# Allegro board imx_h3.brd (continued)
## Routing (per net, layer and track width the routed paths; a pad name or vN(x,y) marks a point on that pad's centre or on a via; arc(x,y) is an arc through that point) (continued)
DDR2_D14: length 15.4
  INT1 w0.12: v1(68.69,44.35) 68.72,44.37 68.72,44.38 68.56,44.22 66.83,44.22 66.71,44.11 66.6,44.11 66.39,43.9 arc(66.28,43.79) 66.17,43.9 66.17,44 arc(66.06,44.11) 65.95,44 65.95,43.9 arc(65.84,43.79) 65.73,43.9 65.73,44 arc(65.62,44.11) 65.51,44 65.51,43.9 arc(65.4,43.79) 65.29,43.9 65.29,44 arc(65.18,44.11) 65.07,44 65.07,43.9 arc(64.96,43.79) 64.85,43.9 64.85,44 arc(64.74,44.11) 64.63,44 64.63,43.9 arc(64.52,43.79) 64.41,43.9 64.41,44 arc(64.3,44.11) 64.19,44 64.19,43.9 arc(64.08,43.79) 63.97,43.9 63.97,44 arc(63.86,44.11) 63.75,44 63.75,43.9 arc(63.68,43.8) 63.56,43.83 63.37,43.83 63.18,43.65 61.55,43.65 61.48,43.71 61.48,44.36 61.36,44.49 61.25,44.49 61.24,44.49 61.24,44.49 61.23,44.5 60.89,44.5 60.88,44.49 60.35,44.49 arc(60.27,44.52) 60.24,44.6 v1(60.24,44.92)
  BOTTOM w0.12: v1(60.24,44.92) 60.16,44.92 59.84,45.24 ; U2.B1 69.56,45.63 69.37,45.45 68.66,45.45 68.5,45.28 68.5,44.55 v1(68.69,44.35)
DDR2_D15: length 15.3
  BOTTOM w0.12: 63.05,45.24 64.01,45.24 64.92,44.33 66.13,44.33 67.09,43.38 67.55,43.38 arc(67.63,43.34) 67.66,43.26 67.66,43.26 arc(67.77,43.15) 67.88,43.26 67.88,43.26 arc(67.91,43.34) 67.99,43.38 74.31,43.38 75.56,44.62 75.56,45.25 75.96,45.66
DDR2_DQM0: length 16.2
  INT1 w0.12: v1(65.93,49.78) 65.77,49.78 65.47,49.47 65.47,49.24 65.18,48.96 64.31,48.96 63.63,49.63 v1(61.82,49.63)
  BOTTOM w0.12: v1(65.93,49.78) 66.23,49.48 66.23,49.19 67.04,48.37 67.19,48.37 arc(67.27,48.34) 67.3,48.26 67.3,47.62 arc(67.41,47.51) 67.52,47.62 67.52,48.26 arc(67.63,48.37) 67.74,48.26 67.74,47.62 arc(67.85,47.51) 67.96,47.62 67.96,48.26 arc(68.07,48.37) 68.18,48.26 68.18,47.63 arc(68.29,47.52) 68.4,47.63 68.4,48.26 arc(68.44,48.34) 68.51,48.37 69.37,48.37 69.41,48.41 70.5,48.41 70.94,48.85 U2.F3 ; v1(61.82,49.63) 61.82,49.7 61.49,50.03 61.45,50.03
DDR2_DQM1: length 15.3
  INT1 w0.12: v1(61.87,44.78) 62.31,44.33 62.53,44.33 arc(62.59,44.3) 62.62,44.24 arc(62.65,44.18) 62.71,44.15 62.75,44.15 arc(62.81,44.18) 62.84,44.24 arc(62.87,44.3) 62.93,44.33 65.57,44.33 arc(65.62,44.34) 65.65,44.36 65.98,44.69 arc(66.01,44.71) 66.06,44.72 66.23,44.72 arc(66.31,44.69) 66.34,44.61 66.34,44.44 arc(66.45,44.33) 66.56,44.44 66.56,44.61 arc(66.67,44.72) 66.78,44.61 66.78,44.56 arc(66.81,44.48) 66.89,44.44 66.92,44.44 arc(66.98,44.47) 67,44.53 67,44.61 arc(67.11,44.72) 67.22,44.61 67.22,44.53 arc(67.24,44.47) 67.3,44.44 67.33,44.44 arc(67.41,44.48) 67.44,44.56 67.44,44.61 arc(67.47,44.69) 67.55,44.72 67.63,44.72 arc(67.67,44.73) 67.71,44.75 67.79,44.84 arc(67.83,44.86) 67.87,44.87 69.03,44.87 v1(69.01,44.87)
  BOTTOM w0.12: v1(61.87,44.78) 61.81,44.82 61.81,44.87 61.45,45.24 ; U2.B3 71.4,45.66 arc(71.48,45.64) 71.54,45.6 72.32,44.83 arc(72.37,44.69) 72.32,44.56 arc(72.18,44.5) 72.04,44.56 71.44,45.16 arc(71.38,45.2) 71.31,45.22 69.42,45.22 69.07,44.87 69.03,44.87 v1(69.01,44.87)
DDR2_DQS0: length 16.4
  INT1 w0.12: v1(72.81,48.28) 72.59,48.51 71.24,48.51 70.78,48.06 arc(70.71,48.03) 70.63,48.06 70.53,48.16 arc(70.37,48.16) 70.37,48 70.47,47.9 arc(70.47,47.75) 70.32,47.75 70.22,47.85 arc(70.06,47.85) 70.06,47.69 70.16,47.59 arc(70.19,47.52) 70.16,47.44 69.85,47.13 arc(69.82,47.1) 69.77,47.09 69.1,47.09 arc(69.03,47.13) 68.99,47.21 68.99,47.29 arc(68.88,47.4) 68.77,47.29 68.77,47.21 arc(68.66,47.09) 68.55,47.21 68.55,47.29 arc(68.44,47.4) 68.33,47.29 68.33,47.21 arc(68.22,47.09) 68.11,47.21 68.11,47.29 arc(68,47.4) 67.89,47.29 67.89,47.21 arc(67.78,47.09) 67.67,47.21 67.67,47.39 arc(67.56,47.5) 67.45,47.39 67.45,47.21 arc(67.34,47.09) 67.23,47.21 67.23,47.39 arc(67.12,47.5) 67.01,47.39 67.01,47.21 arc(66.98,47.13) 66.9,47.09 66.19,47.09 65.56,47.72 v1(65.38,47.72)
  BOTTOM w0.12: v1(72.81,48.28) 73.12,48.28 73.54,48.71 73.95,48.71 74.09,48.85 U2.F7 ; v1(65.38,47.72) 65.38,47.77 64.91,48.24 64.59,48.24 arc(64.48,48.31) 64.35,48.34 63.14,48.34 63.05,48.44
DDR2_DQS0_B: length 16.4
  INT1 w0.12: v1(72.38,47.81) 72.38,48.06 72.17,48.26 71.85,48.26 71.84,48.27 71.37,48.27 71.02,47.92 arc(70.99,47.84) 71.02,47.76 71.22,47.56 arc(71.22,47.41) 71.07,47.41 70.87,47.61 arc(70.79,47.64) 70.71,47.61 69.92,46.81 65.88,46.81 65.67,47.01 v1(65.67,47.02)
  BOTTOM w0.12: v1(72.38,47.81) 72.98,47.81 73.64,48.47 74.74,48.47 U2.E8 ; v1(65.67,47.02) 65.52,47.02 arc(65.48,47.03) 65.44,47.05 65.3,47.2 arc(65.25,47.22) 65.2,47.2 arc(65.16,47.18) 65.11,47.2 65.05,47.26 arc(65.03,47.31) 65.05,47.35 arc(65.07,47.4) 65.05,47.45 64.98,47.51 arc(64.94,47.53) 64.89,47.51 arc(64.85,47.49) 64.8,47.51 64.74,47.57 arc(64.72,47.62) 64.74,47.67 arc(64.76,47.71) 64.74,47.76 64.43,48.07 arc(64.39,48.09) 64.35,48.1 63.66,48.1 arc(63.61,48.08) 63.59,48.02 arc(63.56,47.97) 63.51,47.95 63.44,47.95 arc(63.39,47.97) 63.37,48.02 arc(63.34,48.08) 63.29,48.1 63.22,48.1 arc(63.17,48.08) 63.15,48.02 arc(63.12,47.97) 63.07,47.95 63,47.95 arc(62.95,47.97) 62.93,48.02 arc(62.9,48.08) 62.85,48.1 62.58,48.1 U1.K16
DDR2_DQS1: length 15.2
  BOTTOM w0.12: 63.05,47.63 63.18,47.5 63.24,47.5 63.65,47.09 64.08,47.09 arc(64.12,47.11) 64.14,47.16 arc(64.16,47.21) 64.21,47.22 64.3,47.22 arc(64.34,47.21) 64.36,47.16 arc(64.38,47.11) 64.43,47.09 64.52,47.09 arc(64.56,47.11) 64.58,47.16 arc(64.6,47.21) 64.65,47.22 64.73,47.22 arc(64.78,47.21) 64.8,47.16 64.8,47.09 64.91,47.09 65.45,46.55 65.45,46.56 68.17,43.84 73.94,43.84 74.8,44.7 74.8,45.21 U2.B7
DDR2_DQS1_B: length 15.2
  BOTTOM w0.12: U2.A8 75.16,44.72 74.03,43.59 68.06,43.59 65.2,46.46 64.81,46.85 63.55,46.85 63.2,47.2 62.68,47.2 U1.J16
DDR2_ODT0: length 14.9
  INT1 w0.12: v1(65.45,52.46) 65.54,52.46 65.88,52.8 66.71,52.8 67.05,53.15 67.48,53.15 67.9,52.73 68.63,52.73 arc(68.68,52.71) 68.7,52.66 arc(68.71,52.62) 68.76,52.6 68.85,52.6 arc(68.9,52.62) 68.92,52.66 arc(68.93,52.71) 68.98,52.73 69.07,52.73 arc(69.12,52.71) 69.14,52.66 arc(69.15,52.62) 69.2,52.6 69.29,52.6 arc(69.34,52.62) 69.36,52.66 arc(69.37,52.71) 69.42,52.73 69.51,52.73 arc(69.56,52.71) 69.58,52.66 arc(69.59,52.62) 69.64,52.6 69.73,52.6 arc(69.78,52.62) 69.8,52.66 arc(69.81,52.71) 69.86,52.73 69.95,52.73 arc(70,52.71) 70.02,52.66 arc(70.03,52.62) 70.08,52.6 70.17,52.6 arc(70.22,52.62) 70.24,52.66 arc(70.25,52.71) 70.3,52.73 70.39,52.73 arc(70.44,52.71) 70.46,52.66 arc(70.47,52.62) 70.52,52.6 70.61,52.6 arc(70.66,52.62) 70.68,52.66 arc(70.69,52.71) 70.74,52.73 70.83,52.73 arc(70.88,52.71) 70.9,52.66 arc(70.91,52.62) 70.96,52.6 71.05,52.6 arc(71.1,52.62) 71.12,52.66 arc(71.13,52.71) 71.18,52.73 71.27,52.73 arc(71.32,52.71) 71.34,52.66 arc(71.35,52.62) 71.4,52.6 71.49,52.6 arc(71.54,52.62) 71.56,52.66 arc(71.57,52.71) 71.62,52.73 v1(72.63,52.73)
  BOTTOM w0.12: v1(65.45,52.46) 65.18,52.46 65.06,52.34 64.52,52.34 64.33,52.15 63.33,52.15 63.05,52.44 ; v1(72.63,52.73) 73.29,52.73 73.52,52.5 75.5,52.5 75.94,52.06 75.96,52.06
DDR2_OPEN: length 19.1
  INT1 w0.12: v1(60.2,48) 60.2,48 60.55,47.65 61.6,47.65 61.65,47.7 62.05,47.7 62.1,47.65 62.13,47.65 62.58,47.2 62.95,47.2 63,47.15 64.15,47.15 65.14,48.15 65.62,48.15 66.31,48.84 66.97,48.84 67.32,49.19 67.32,49.67 67.06,49.93 66.66,49.93 65.47,48.74 64.22,48.74 63.55,49.4 62.17,49.4 62,49.22 61.64,49.22 61.22,49.65 v1(60.22,49.65)
  BOTTOM w0.12: 61.45,49.24 61.39,49.24 61.05,49.58 60.28,49.58 v1(60.22,49.65) ; U1.K14 60.63,48.44 60.2,48 v1(60.2,48)
DDR2_RAS_B: length 15.3
  INT1 w0.12: v1(66.2,51.97) 66.28,52.06 68,52.06 68.23,52.29 v1(72.03,52.29)
  BOTTOM w0.12: v1(66.2,51.97) 66.2,52.31 65.62,52.88 65.28,52.88 64.97,52.56 64.42,52.56 64.23,52.37 63.73,52.37 63.28,52.82 62.66,52.82 62.27,52.44 U1.R16 ; U2.K7 74.12,52.06 73.94,52.23 arc(73.91,52.25) 73.86,52.26 73.53,52.26 arc(73.45,52.23) 73.42,52.15 73.42,52.03 arc(73.31,51.93) 73.2,52.03 73.2,52.39 arc(73.09,52.5) 72.98,52.39 72.98,51.84 arc(72.87,51.74) 72.76,51.84 72.76,52.15 arc(72.73,52.23) 72.65,52.26 72.06,52.26 v1(72.03,52.29)
DDR2_VREF: length 13.4
  PWR w0.1: 61.05,52.92 v1(61.05,52.92)
  BOTTOM w0.1: v1(66.7,51.29) 66.84,51.29 67,51.45 68.5,51.45 68.8,51.75 69.2,51.75 69.35,51.6 69.7,51.6 70.05,51.25 U2.J2 ; R2.2 57.7,56.65 C25.1 ; R2.2 57.71,56.51 C24.2 ; R2.2 56.95,56.5 56.92,56.48 ; v1(59.41,48.05) 59.41,48.05 59.41,48.06 59.39,48.06 59.39,48.05 59.42,48.01 ; R3.1 56.92,56.48 ; R3.1 56.91,56.63 C24.2 ; R3.1 56.91,56.04 v1(56.53,55.66) ; 56.92,56.48 C25.1 ; C25.1 56.92,57.95 56.91,57.96 ; C25.1 C24.2 ; U1.R14 61.05,52.84 v1(61.05,52.92) ; C24.2 57.71,57.95 57.69,57.97
  BOTTOM w0.3: 59.42,48.01 U1.K13
DDR2_WE_B: length 13.5
  INT1 w0.12: v1(64.92,54.16) 65.05,54.16 65.95,53.26 v1(65.95,53.22)
  BOTTOM w0.12: U2.K3 71.16,52.04 70.72,51.61 70.11,51.61 69.73,51.99 68.58,51.99 arc(68.53,51.97) 68.51,51.92 arc(68.49,51.87) 68.44,51.85 68.36,51.85 arc(68.31,51.87) 68.29,51.92 arc(68.27,51.97) 68.22,51.99 68,51.99 arc(67.92,51.95) 67.89,51.88 67.89,51.77 arc(67.78,51.66) 67.67,51.77 67.67,51.88 arc(67.56,51.99) 67.45,51.88 67.45,51.77 arc(67.34,51.66) 67.23,51.77 67.23,51.88 arc(67.2,51.95) 67.12,51.99 66.9,51.99 66.37,52.51 66.37,52.51 66.1,52.78 66.1,53.1 65.95,53.25 v1(65.95,53.22) ; 61.45,53.24 61.45,53.31 61.81,53.68 61.81,54.09 62.54,54.82 64.03,54.82 64.1,54.76 64.1,54.76 64.34,54.52 64.53,54.32 64.77,54.32 v1(64.92,54.16)
DEBUG_GND: length 23.7
  TOP w0.3: R208.2 121.25,5.6 120.84,5.19 J8.S2 120.25,4.74 J8.5
  GND2 w0.3: v2(114.45,1.74) 114.45,2.79 114.73,3.08 115.82,4.16 115.86,4.22 115.9,4.25 115.9,4.4 116.24,4.74 J8.S1 J8.S2 122.8,2.78 v2(122.8,1.74)
  BOTTOM w0.1: 119.61,6.97 C305.2 119.61,5.53 ; J8.S2 121.53,4.74 ; J8.S2 120.84,5.58 ; J8.S2 120.84,3.89 ; J8.S2 120.16,4.74 ; 116.4,3.89 J8.S1 ; J8.S1 115.71,4.74 ; J8.S1 117.08,4.74 ; J8.S1 116.4,5.58
  BOTTOM w0.3: v1(120.45,5.8) 120,6.25 C305.2
DUAL_GND: length 48
  BOTTOM w0.1: 33.72,12.84 J22.B4 ; J22.B4 34.67,11.89 ; J22.B4 35.62,12.84 ; 37.74,8.08 J22.S4 ; J22.S4 35.7,10.12 ; J22.S4 37.74,12.16 ; J22.S4 39.79,10.12 ; 35.7,15.81 J22.S2 ; J22.S2 37.74,13.77 ; J22.S2 37.74,17.85 ; J22.S2 39.79,15.81 ; J22.A4 34.67,16.4 ; J22.A4 35.62,15.45 ; J22.A4 33.72,15.45 ; L23.2 33.96,8.39 ; L23.2 33.4,9.04 ; L23.2 32.84,8.39 ; J22.S3 24.61,12.16 ; J22.S3 26.65,10.12 ; J22.S3 22.57,10.12 ; J22.S3 24.61,8.08 ; J22.S1 24.61,17.85 ; J22.S1 22.57,15.81 ; J22.S1 26.65,15.81 ; J22.S1 24.61,13.77
  BOTTOM w0.3: L25.2 34.05,18.75 ; L25.2 33.49,18.1 ; L25.2 32.93,18.75 ; J22.A4 J22.B4
  BOTTOM w0.5: 27.75,8.7 28.46,7.99 C302.2 ; L25.2 33.39,18.85 C303.2
DUART_RX: length 95.8
  TOP w0.1: v1(43.8,42.56) 43.8,42.75 46.6,45.55 46.6,48.21 46.91,48.52 47.35,48.52 47.53,48.34 48.3,48.34 48.77,48.81 50.94,48.81 51.3,48.45 52.67,48.45 53.05,48.82 v1(53.05,48.91)
  INT1 w0.1: v1(56.17,27) 56.45,27 57.53,25.93 57.53,25.62 59.18,23.97 60.53,23.97 60.87,23.97 61.58,23.26 61.91,23.26 82.98,23.26 83.36,22.89 83.36,22.88 83.7,22.54 85.68,22.54 89.13,22.54 89.14,22.53 91.4,22.53 92.56,23.69 94.48,23.69 95.23,22.94 95.56,22.94 95.97,23.34 96.48,23.34 102.89,16.94 v1(102.89,15.09)
  BOTTOM w0.1: 55.05,48.44 54.69,48.44 54.29,48.03 54.05,48.03 53.88,48.21 53.88,48.56 53.53,48.91 v1(53.05,48.91) ; v1(102.89,15.09) 104.14,15.09 Q19.2 104.3,15.24 R213.1 ; v1(56.17,27) 56.13,27 55.66,27.47 55.66,27.49 55.66,27.49 55.66,27.66 55.66,27.66 54.78,28.53 54.5,28.53 50.89,32.15 50.33,32.15 50.33,32.15 49.55,32.15 45.78,35.91 45.78,36.66 45.79,36.66 45.79,36.83 45.78,36.83 45.77,36.85 45.77,36.92 44.77,37.91 44.06,37.91 43.3,38.67 43.3,39.33 43.29,39.33 43.29,39.84 43.3,39.84 43.3,41.83 43.8,42.33 v1(43.8,42.56)
DUART_TX: length 94.5
  TOP w0.1: v1(86.25,29.75) 86.25,29.79 85.08,30.96 85.08,32.03 84.96,32.15 v1(84.96,32.23) ; v1(54.7,49.59) 54.7,49.69 55.56,50.56 55.56,50.68 55.86,50.97 55.86,51.46 55.87,51.47 55.87,52.36 56.12,52.61 56.12,56.03 56.1,56.05 56.1,56.4 60.3,60.6 62.23,60.6 62.43,60.41 70.94,60.41 70.95,60.4 76.3,60.4 80.85,55.85 80.85,51.06 83.14,48.78 83.14,47.68 83.12,47.66 83.12,46.63 v1(83.05,46.56)
  INT1 w0.1: v1(102.48,14.53) 102.48,14.68 95.89,21.26 v1(91.93,21.26) ; v1(84.96,32.23) 85.23,32.5 85.23,34.66 86.17,35.61 86.17,37.9 86.17,37.91 86.17,39.21 85.18,40.21 85.18,42.93 83.08,45.03 83.08,46.53 v1(83.05,46.56)
  BOTTOM w0.1: v1(91.93,21.26) 90.43,22.77 88.21,22.77 86.79,24.19 86.79,29.28 86.32,29.75 v1(86.25,29.75) ; v1(102.48,14.53) 102.98,14.53 103.39,14.12 103.39,13.29 104.17,12.51 Q17.2 ; 55.05,49.24 v1(54.7,49.59)
EN_BOT: length 25.2
  TOP w0.1: v1(26.52,34.95) 26.45,35.01 26.14,35.01 25.73,34.61 25.73,34.07 26.05,33.75 26.05,29.85 25.1,28.9 25.1,26.85 24.75,26.5 22.7,26.5 v1(22.4,26.2) 22.4,26.85 19.65,29.6 v1(17.45,29.6)
  BOTTOM w0.1: v1(26.52,34.95) 27.17,34.95 27.42,34.7 U25.18 ; U40.4 14.95,28.05 14.95,29.1 15.45,29.6 v1(17.45,29.6) ; v1(22.4,26.2) 22.4,26.1 22.19,25.89 U32.4
EN_MODEM: length 87.5
  TOP w0.1: v1(80.71,19.98) 80.77,19.98 80.97,19.78 80.97,10.84 81.16,10.64 81.16,9.97 v1(81.29,9.85) ; v1(36.81,25.67) 36.67,25.81 36.67,26.12 36.44,26.36 27.74,26.36 25.86,28.24 v1(25.86,28.29)
  INT1 w0.1: v1(36.81,25.67) 36.81,24.73 39.97,21.57 60.32,21.57 61.89,21.57 62.13,21.33 v1(62.14,21.33)
  BOTTOM w0.1: v1(80.71,19.98) 80.69,19.98 80.69,19.96 80.76,19.96 80.73,19.99 80.73,20.32 80.14,20.91 72.17,20.91 70.97,19.71 68.54,19.71 68.31,19.95 68.3,19.95 67.77,20.49 62.98,20.49 v1(62.14,21.33) ; U33.4 82.94,8.45 82.7,8.45 81.3,9.85 v1(81.29,9.85) ; U40.12 15.62,32.92 18.65,29.89 23.01,29.89 24.61,28.29 U31.4 25.06,28.29 R108.2 25.88,28.32 v1(25.86,28.29)
EN_TOP: length 24.4
  TOP w0.1: v1(26.91,29.49) 26.91,30.44 27.23,30.76 27.23,33.38 v1(26.91,33.7)
  BOTTOM w0.1: U32.3 21.41,24.59 20.03,25.97 ; 20.03,25.97 15.41,25.97 14.31,27.08 U40.5 ; 20.03,25.97 20.03,26 20.38,26.35 21.85,26.35 22.15,26.65 25.42,26.65 26.56,27.79 26.56,29.15 26.89,29.49 v1(26.91,29.49) ; v1(26.91,33.7) U25.16
ENET_CLKO: length 4.9
  BOTTOM w0.1: 51.05,44.44 50.85,44.44 50.55,44.13 50.12,44.13 49.84,44.42 49.84,44.58 49.39,45.03 48.02,45.03 47.57,45.47 46.94,45.47 R180.1
ENET_INT: length 54.8
  INT1 w0.1: v1(37.86,46.47) 38.3,46.91 38.3,57.22 38.74,57.66 38.74,60.86 44.3,66.42 44.3,68.01 44.78,68.49 45.42,68.49 47.25,70.32 v1(47.25,70.45)
  BOTTOM w0.1: U3.14 37.28,45.97 R13.1 37.33,45.94 v1(37.86,46.47) ; v1(47.25,70.45) 47.68,70.45 49.03,71.8 59.22,71.8 59.22,71.8 59.54,71.8 60.61,70.74 61.31,70.03 61.31,67.76 64.6,64.47 65.84,64.47 66.13,64.76 U17.11
ENET_MDC: length 8.8
  BOTTOM w0.1: R182.1 44.64,47 47.17,47 48.52,45.65 52.34,45.65 52.64,45.95 U1.G4
ENET_MDIO: length 7.2
  TOP w0.1: v1(52.3,47.26) 52.22,47.26 51.75,47.73 50.21,47.73 49.83,47.35 49.47,47.35 v1(48.57,46.46)
  BOTTOM w0.1: v1(48.57,46.46) 48.43,46.6 48.15,46.6 47.28,47.47 R181.1 ; 52.64,46.84 52.55,46.84 52.3,47.09 52.3,47.25 v1(52.3,47.26)
ENET_RESET_B: length 59.5
  INT1 w0.1: v1(45.23,69.09) 45.14,68.99 45,68.99 44.1,68.1 44.1,66.5 38.55,60.94 38.55,57.75 38.09,57.3 38.09,47.56 37.34,46.79 37.34,46.32 v1(36.52,45.5)
  BOTTOM w0.1: U17.7 68.13,64.16 67.62,63.65 64.77,63.65 60.82,67.59 60.82,69.06 60.82,69.06 60.82,69.96 60.23,70.55 59.38,71.4 49.2,71.4 47.57,69.77 47,69.77 47,69.78 46.63,69.78 45.95,69.09 v1(45.23,69.09) ; U3.15 36.01,45.47 36.47,45.01 37.28,45.01 R12.2 37.02,45 v1(36.52,45.5)
ENET_RXD0: length 4.1
  BOTTOM w0.1: R183.1 47.14,48.21 47.51,48.21 48.58,47.13 49.77,47.13 50.06,46.84 50.24,46.84
ENET_RXD1: length 7.2
  BOTTOM w0.1: 51.05,46.84 51.05,46.79 50.74,46.49 50.13,46.49 49.68,46.93 48.5,46.93 47.44,47.99 R184.1
ENET_RXEN: length 18.5
  TOP w0.1: v1(40.83,47.67) 40.83,45.57 41.98,44.42 41.99,44.42 42.73,43.68 42.73,42.31 43.61,41.44 45.7,41.44 46.28,42.02 47.7,42.02 48.21,42.53 48.21,42.54 48.44,42.76 48.98,42.76 50.16,43.95 51.4,43.95 51.41,43.95 v1(51.44,43.95)
  BOTTOM w0.1: v1(40.83,47.67) R185.1 ; U1.E4 52.15,43.94 51.45,43.94 v1(51.44,43.95)
ENET_TXD0: length 3.9
  BOTTOM w0.1: 50.24,45.24 49.78,45.24 49.59,45.43 48.18,45.43 47.12,46.49 R186.1
ENET_TXD1: length 7
  BOTTOM w0.1: 51.05,45.24 51.04,45.24 50.73,44.93 50.46,44.93 50.46,44.93 50.03,44.93 50.03,44.93 49.8,44.93 49.5,45.22 48.1,45.22 47.34,45.99 R187.1
ENET_TXEN: length 14.8
  TOP w0.1: v1(51.5,44.81) 51.5,44.8 51.16,44.45 49.3,44.45 v1(49.25,44.5) 48.61,43.85 48.61,43.29 48.04,42.72 48.04,42.72 47.54,42.22 46.2,42.22 45.62,41.64 44.14,41.64 43.63,42.16 43.31,42.47 43.31,43.93 43.65,44.26 43.65,44.27 v1(43.64,44.28)
  BOTTOM w0.1: v1(43.64,44.28) 43.79,44.43 44.15,44.43 R188.1 ; 52.64,45.24 52.23,44.82 51.57,44.82 51.56,44.81 v1(51.5,44.81)
ETH_RXN: length 39.1
  TOP w0.12: v1(51.9,24.25) 51.84,24.19 51.84,18.39 T1.6
  INT1 w0.12: v1(33.59,42.54) 33.59,42.16 34.52,41.22 38.96,41.22 42.03,38.15 42.62,38.15 51.66,29.11 51.66,24.49 v1(51.9,24.25)
  BOTTOM w0.12: R5.2 34.32,41.42 33.59,42.16 v1(33.59,42.54) U3.22
ETH_RXP: length 42.1
  TOP w0.12: T1.3 50.13,14.4 51.91,16.18 51.91,17.98 51.59,18.29 51.59,23.96 51.27,24.28 v1(51.24,24.28)
  INT1 w0.12: v1(33.09,42.14) 33.26,42.14 34.42,40.98 38.87,40.98 41.94,37.91 42.52,37.91 51.42,29.01 51.42,24.46 v1(51.24,24.28)
  BOTTOM w0.12: U3.23 v1(33.09,42.14) 33,42.06 33,41.74 R4.2
ETH_TXN: length 33.7
  TOP w0.12: T1.2 48.02,17.13 48.02,23.76 v1(48.17,23.91)
  INT1 w0.12: v1(48.17,23.92) 48.17,24.31 48.19,24.33 48.19,29.97 38.68,39.49 v1(38.68,40.34)
  BOTTOM w0.12: U3.20 34.59,42.56 35.15,42 35.43,42 ; v1(38.68,40.34) 38.38,40.34 37.67,41.05 36.36,41.05 36.21,41.21 36.19,41.21 35.98,41.43 35.98,41.46 35.97,41.47 35.96,41.47 35.43,42 ; 35.43,42 35.68,42.25 R8.2
ETH_TXP: length 36.3
  TOP w0.12: T1.1 46.98,14.45 46.98,17.22 47.76,18 47.76,23.74 47.76,23.74 47.76,24.29 v1(47.72,24.33)
  INT1 w0.12: v1(47.72,24.33) 47.95,24.55 47.95,29.88 37.92,39.9 v1(37.92,40)
  BOTTOM w0.12: v1(37.92,40) 37.92,40.14 37.37,40.7 36.37,40.7 36.26,40.81 36.11,40.97 36.09,40.97 35.66,41.41 35.57,41.41 ; 35.35,41.63 35.35,41.69 35.28,41.76 35.05,41.76 34.18,42.63 34.18,42.9 34.09,43 34.09,43.26 U3.21 ; 35.35,41.63 35.57,41.41 ; 35.35,41.63 R7.2 35.57,41.41
FEC_A3V3: length 51.8
  TOP w0.1: v1(49.62,28.11) 49.62,21.47 48.88,20.74 48.88,20.37 48.91,20.34 v1(48.95,20.34)
  BOTTOM w0.1: 28.36,44.7 L1.1 ; L1.1 28.92,45.35 ; L1.1 28.92,44.06 ; L1.1 29.48,44.7 ; 28.47,42.97 C247.1 28.94,43.44 ; v1(49.62,28.11) 49.62,28.53 39.66,38.49 39.57,38.49 39.21,38.85 34.48,38.85 32.92,40.41 R4.1 ; 34.48,40.41 35.34,40.41 R7.1 35.74,40.39 v1(36.02,40.12) ; R10.2 46.45,20.34 v1(48.95,20.34) R6.1
  BOTTOM w0.3: R8.1 36.7,42.17 C30.1 36.4,41.72 36.38,41.71 v1(36.38,41.69) ; R8.1 36.02,43.09 35.25,43.09 U3.19 ; R8.1 36.91,42.63 38.3,42.63 C252.1 ; U3.1 31.77,44.07 C248.1 30.29,43.38 C27.1 ; R4.1 C28.1 31.84,40.41 31.01,40.41 30.42,40.99 v1(30.42,41.03) ; C27.1 29.4,43.38 29.05,43.73 v1(29.05,43.74) 29.05,44.57 L1.1 ; C27.1 29.22,42.97 C247.1
HP_GND: length 30.7
  INT1 w0.3: 113.52,35.5 113.52,40.94 J15.2 ; 113.52,35.5 121.96,35.5 J18.1 ; 113.52,35.5 111.74,33.72 108.95,33.72 106.32,36.35 105.93,36.35 105.3,36.99 102.66,36.99 102.19,37.46 v1(102.19,38.41)
  BOTTOM w0.3: L13.1 101.75,39.06 101.76,39.06 102.13,38.69 102.13,38.47 v1(102.19,38.41) 102.31,38.29 U19.4
HP_L: length 22.1
  TOP w0.3: J15.1 114.23,39.65 J18.3 ; v1(103.31,38.07) 103.57,38.07 103.6,38.04 103.99,38.04 108.71,33.33 v1(108.71,33.25)
  BOTTOM w0.3: v1(108.71,33.25) 109.21,33.25 C267.1 C213.1 113.92,33.64 J18.3 ; U19.6 v1(103.31,38.07)
HP_R: length 24.2
  TOP w0.3: v1(108.59,39.05) 104.61,39.05 104.61,39.05 101.71,39.05 101.48,38.82 v1(101.48,38.26)
  BOTTOM w0.3: v1(101.48,38.26) 101.31,38.08 101.31,37.34 ; J18.2 118.19,34.88 117,34.88 111.54,40.34 J15.3 110.13,39.55 C268.1 109.97,39.54 C212.1 109.08,39.54 v1(108.59,39.05)
I2C_SCL: length 202.6
  TOP w0.1: 41.92,38.99 42.38,38.99 43.4,40.01 45.02,40.01 46.53,38.51 50.14,38.51 52.83,41.2 53.59,41.2 54.23,41.84 54.23,41.86 54.46,42.1 54.48,42.1 54.67,42.28 v1(54.67,42.38) ; 41.92,38.99 41.92,38.98 41.59,38.98 40.24,37.64 35.16,37.64 34.45,38.35 v1(34.45,38.36) ; 41.92,38.99 v1(41.92,38.99) ; v1(40.25,40.87) 40.1,41.02 40.1,41.85 40.12,41.87 40.12,44.67 39.89,44.9 v1(39.89,44.91)
  INT1 w0.1: v1(64.56,70.81) 64.55,70.79 60.21,70.79 59.17,71.83 50.37,71.83 40.21,61.67 40.21,56.77 39.49,56.05 39.49,45.96 39.88,45.56 39.88,44.91 v1(39.89,44.91) ; v1(54.15,27.44) 54.2,27.49 54.2,27.5 55.02,28.33 56.59,28.33 60.01,24.91 60.5,24.91 61.06,24.91 61.91,24.06 68.81,24.06 69.65,24.06 69.66,24.07 69.99,24.07 70,24.06 70.51,24.06 75.47,24.06 76.88,24.06 80.02,24.06 80.03,24.06 80.36,24.06 82.12,24.06 83.32,24.06 84.04,23.34 87.62,23.34 87.66,23.38 88,23.38 88.46,23.84 88.97,23.84 89.1,23.71 89.74,23.71 v1(89.78,23.68)
  BOTTOM w0.1: v1(64.56,70.81) 64.56,70.81 64.56,70.79 ; 55.05,42.84 55.05,42.78 54.67,42.4 v1(54.67,42.38) ; R104.2 64.34,71.01 64.56,70.79 ; U19.29 99.38,35.19 98.95,34.75 98.95,34.34 95.54,30.94 95.09,30.94 89.78,25.62 v1(89.78,23.68) ; v1(40.25,40.87) 40.26,40.87 41.32,39.81 41.32,39.59 41.92,38.99 v1(41.92,38.99) 41.92,38.98 41.92,38.63 42.12,38.43 42.12,38.43 42.29,38.26 42.29,38.26 43.6,36.94 43.6,36.85 45.1,35.36 45.1,35.25 45.83,34.52 45.83,34.51 47.99,32.35 47.99,32.35 49.01,31.34 49.38,31.34 49.38,31.34 50.49,31.34 50.49,31.34 50.5,31.34 53.84,28 53.84,27.74 v1(54.15,27.44) ; U4.24 14.27,65.12 12.13,62.98 12.13,57.09 13.34,55.88 13.34,55.88 13.92,55.29 19.3,55.29 21.77,52.81 24.82,52.81 26.14,51.49 26.14,46.94 26.61,46.47 26.61,46.46 27.92,45.15 27.92,44.82 27.92,41.47 29.24,40.14 29.8,40.14 30.24,39.7 33.12,39.7 34.45,38.37 v1(34.45,38.36) 34.44,38.37 34.41,38.37 33.97,38.8 32,38.8 31.35,38.15 R95.2 ; U17.19 65.63,69.32 65.7,69.39 65.7,70.31 65.22,70.79 64.56,70.79
I2C_SDA: length 205.6
  TOP w0.1: v1(39.44,41.44) 39.55,41.56 39.55,43.82 v1(39.72,43.98) ; v1(55.43,43.24) 55.42,43.22 55.34,43.22 54.92,42.81 54.5,42.81 54.26,42.57 54.26,42.18 54.02,41.94 54.02,41.94 54.02,41.93 54.02,41.91 53.5,41.4 52.75,41.4 50.06,38.71 46.61,38.71 45.76,39.56 45.47,39.85 45.11,40.21 42.97,40.21 42.51,39.75 v1(41.77,39.75) 41.75,39.75 39.84,37.84 35.56,37.84 34.63,38.76 31.48,38.76 30.53,39.72 29.68,39.72 29.67,39.71 v1(29.67,39.71) 29.66,39.7 29.66,39.63 29.11,39.09 v1(29.11,39.03)
  INT1 w0.1: v1(39.72,43.98) 39.55,44.15 39.55,44.33 39.29,44.59 39.29,56.13 40.01,56.85 40.01,61.46 40.01,61.46 40.01,61.84 44.5,66.33 44.5,66.35 50.17,72.03 59.77,72.03 60.73,71.08 64.03,71.08 v1(64.44,71.49) ; v1(54.76,27.41) 54.83,27.48 54.83,27.48 55.47,28.12 56.52,28.12 59.93,24.71 59.99,24.71 60.98,24.71 61.83,23.86 83.24,23.86 83.96,23.14 87.8,23.14 87.84,23.18 88.08,23.18 88.55,23.64 88.88,23.64 89.12,23.41 89.12,23.4 v1(89.33,23.19)
  BOTTOM w0.1: v1(39.44,41.44) 39.49,41.39 40.33,41.39 40.93,40.78 40.95,40.78 41.77,39.97 v1(41.77,39.75) 41.77,39.71 42.33,39.16 42.33,38.51 42.48,38.35 42.48,38.34 43.8,37.03 43.8,36.94 45.37,35.38 45.37,35.27 46.03,34.6 46.03,34.6 48.07,32.56 48.08,32.56 49.09,31.54 49.64,31.54 49.65,31.54 50.58,31.54 54.32,27.81 54.35,27.81 54.75,27.41 v1(54.76,27.41) ; U19.27 100.16,34.19 99.07,34.19 95.62,30.74 95.18,30.74 90.18,25.74 90.18,23.51 89.87,23.19 v1(89.33,23.19) ; v1(29.11,39.03) 29.06,38.99 R94.2 ; v1(55.43,43.24) 55.43,43.24 55.82,43.63 U1.D8 ; U17.20 66.13,69.31 65.9,69.53 65.9,70.39 65.3,70.99 65,70.99 64.52,71.47 64.45,71.47 v1(64.44,71.49) 63.49,71.49 63.42,71.42 63.27,71.42 62.96,71.11 R105.2 ; U4.25 13.69,65.62 11.8,63.74 11.8,56.97 13.68,55.09 19.12,55.09 21.6,52.62 24.73,52.62 25.95,51.41 25.95,46.85 26.41,46.39 26.41,46.38 27.45,45.34 27.45,45.34 27.72,45.07 27.72,41.19 29.15,39.75 29.62,39.75 v1(29.67,39.71)
IO_EXP_INT_B: length 50.8
  TOP w0.1: v1(52.99,56.83) 52.96,56.79 52.96,56.09 54.78,54.26 54.78,52.56 55.05,52.29 55.05,51.57 55.37,51.26 v1(55.37,51.23)
  INT1 w0.1: v1(63.18,72.03) 62.03,72.03 61.83,72.23 50.48,72.23 49.83,72.23 44.98,67.37 v1(44.8,67.37)
  BOTTOM w0.1: 55.84,50.84 55.45,51.23 v1(55.37,51.23) ; v1(52.99,56.83) 52.99,57.06 53.31,57.38 53.31,58.44 51.66,60.1 51.66,60.84 51.52,60.98 51.52,61.81 45.95,67.37 v1(44.8,67.37) ; R109.2 65.56,72.78 ; 65.56,72.78 66.34,72.78 67.13,71.99 U17.22 ; 65.56,72.78 64.39,72.78 63.64,72.03 v1(63.18,72.03)
ISM_DIO5: length 5.3
  TOP w0.1: TP8.1 21.36,62.01 v1(21.36,61) 22.27,61 v1(22.72,61.44)
  BOTTOM w0.1: U4.54 23.61,61.44 v1(22.72,61.44) ; U4.5 21.16,60.79 v1(21.36,61)
ISM_DIR: length 4.5
  TOP w0.1: v1(18.18,68.66) 18.5,68.66 18.77,68.94 20.33,68.94 v1(20.51,68.75)
  BOTTOM w0.1: v1(18.18,68.66) 18.16,68.65 18.16,67.74 ; U4.37 20.66,68.61 v1(20.51,68.75)
ISM_GPIO: length 62.4
  TOP w0.1: v1(16.95,59.18) 17.23,59.46 21.46,59.46 21.63,59.28 23.52,59.28 24.58,59.28 25.07,59.78 27.25,59.78 27.9,60.42 27.9,60.45 28.57,61.12 28.59,61.12 28.83,61.36 28.83,61.36 29.01,61.54 29.01,61.56 29.09,61.64 29.09,65.42 34.12,70.44 35.59,70.44 v1(35.63,70.49)
  BOTTOM w0.1: v1(35.63,70.49) 35.95,70.49 36.7,71.24 38.22,71.24 38.57,71.58 38.57,71.6 38.83,71.87 40.76,71.87 42.45,70.18 46.12,70.18 47.3,71.36 47.3,71.93 47.78,72.4 59.47,72.4 59.47,72.4 59.79,72.4 61.28,70.91 61.95,70.24 61.95,67.97 63.68,66.24 U17.14 ; v1(16.95,59.18) 16.66,59.47 16.66,59.99
ISM_LED: length 95.4
  INT1 w0.1: v1(20.35,57.95) 20.35,54.65 21.5,53.5 21.75,53.5 22.05,53.8 27.15,53.8 28.35,55 28.75,55 31.3,57.55 31.3,57.6 35.4,57.6 35.7,57.9 35.7,58.55 35.65,58.6 35.65,58.95 35.7,59 35.7,62.7 35.6,62.8 35.6,63.15 35.7,63.25 35.7,65.85 35.55,66 35.55,66.35 35.8,66.6 36.15,66.6 36.17,66.57 36.2,66.6 38.25,66.6 44.5,72.85 45.45,72.85 45.45,73.05 45.7,73.3 46.05,73.3 46.45,72.9 71.6,72.9 72.05,72.45 78.8,72.45 79.25,72.9 80.25,72.9 81.5,74.15 81.55,74.15 82.6,75.2 82.6,78.25 82.65,78.25 83.75,79.35 83.75,80.05 83.95,80.25 84.25,80.25 84.65,80.65 84.65,81.2 v1(84.8,81.35)
  BOTTOM w0.1: v1(84.8,81.35) 84.8,82.6 85.4,83.2 R206.1 ; v1(20.35,57.95) 19.66,58.65 U4.8
ISM_RESET_B: length 67.3
  TOP w0.1: v1(38.97,71.44) 38.76,71.23 38.76,70.8 38.55,70.59 R66.1 ; J11.4 15.76,65 16.36,65.59 16.36,65.6 17.25,66.5 v1(18.93,66.5) 20.87,66.5 21.76,65.6 28.68,65.6 29.16,66.09 29.19,66.09 29.2,66.09 v1(29.19,66.09)
  BOTTOM w0.1: 38.8,71.47 38.83,71.44 v1(38.97,71.44) ; 38.8,71.47 38.74,71.47 38.3,71.03 36.95,71.03 36.95,71.03 36.79,71.03 35.76,70 35.52,70 35.44,69.93 33.23,69.93 33.12,69.81 33.12,69.81 29.62,66.32 29.4,66.09 v1(29.19,66.09) ; 38.8,71.47 40.31,71.47 41.81,69.97 47.08,69.97 47.09,69.97 47.49,69.97 49.12,71.6 58.9,71.6 59.14,71.6 59.14,71.6 59.46,71.6 60.37,70.69 61.12,69.94 61.12,67.6 64.61,64.1 64.64,64.06 64.85,63.85 67.45,63.85 67.63,64.03 U17.8 ; 18.66,67.74 18.66,67.1 18.93,66.82 v1(18.93,66.5)
ISM_RF_RESET: length 9.5
  TOP w0.1: v1(20.44,60.81) 20.44,61.31 21.02,61.88 21.02,62.52 21.56,63.06 21.96,63.06 v1(22.48,63.58)
  BOTTOM w0.1: v1(22.48,63.58) 22.85,63.58 23.09,63.82 23.09,64.59 23.06,64.62 U4.48 ; v1(20.44,60.81) 20.25,60.62 17.84,60.62 17.66,60.44 17.66,59.99
ISM_RFIO: length 1.9
  BOTTOM w0.3: L7.1 21.66,69.63 U4.39
ISM_UART_RX: length 2.1
  BOTTOM w0.1: TP14.1 U4.15
ISM_UART_TX: length 3.1
  BOTTOM w0.1: TP13.1 13.61,61.19 13.63,61.21 14.13,61.21 14.16,61.19 14.87,61.19 14.89,61.16 15.98,61.16 U4.16
ISM_XTA: length 6.8
  BOTTOM w0.1: U4.46 24.21,65.62 24.79,65.04 24.79,63.97 25.11,63.65 25.94,63.65 27.16,64.87 Y4.1 27.42,64.63 C171.1
ISM_XTB: length 6.8
  BOTTOM w0.1: 25.59,62.71 25.59,62.77 24.59,63.77 24.59,64.75 24.21,65.12 U4.47 ; 25.59,62.71 25.59,62.67 ; 25.59,62.71 26.54,63.66 28.55,63.66 C172.2
JTAG_MX_TDI: length 62.9
  TOP w0.1: v1(56.84,33.31) 56.84,34.29 58.01,35.47 58.01,38.14 58.02,38.14 58.02,38.65 58,38.68 58,41.07 58.19,41.26 58.19,41.63 58.2,41.65 58.2,42.58 58.62,43 v1(58.62,44.02) ; v1(86.91,41.64) 86.89,41.64 85.68,40.43 83.91,40.43 83.08,39.6 v1(83.08,39.21) ; v1(91.05,42.85) 92.23,42.85 92.39,42.69 92.39,41.23 ; v1(84.28,37.6) 84.1,37.42 84.1,33.78 79.02,28.7 62.06,28.7 59.99,30.76 v1(59.99,31.14)
  BOTTOM w0.1: v1(86.91,41.64) 86.89,41.66 86.89,42.18 87.62,42.91 90.99,42.91 v1(91.05,42.85) ; v1(84.28,37.6) 83.89,37.6 82.94,38.55 82.94,39.06 v1(83.08,39.21) ; v1(58.62,44.02) 58.64,44.04 58.64,44.07 59,44.44 59.05,44.44 ; v1(59.99,31.14) 59.18,31.95 58.19,31.95 57.02,33.12 57.02,33.12 v1(56.84,33.31)
JTAG_MX_TDO: length 60.6
  TOP w0.1: R160.2 90.88,43.36 90.56,43.03 90.56,40.29 R163.2 89.77,39.5 85.46,39.5 85.11,39.15 85.11,33.93 79.27,28.1 61.77,28.1 58.38,31.49 58.38,32.71 58.82,33.15 58.82,33.86 58.81,33.86 58.81,34.71 58.82,34.71 58.82,35.18 58.81,35.18 58.81,37.81 58.82,37.81 58.82,38.28 59.22,38.68 59.22,39.44 59.52,39.74 59.53,39.74 60.19,40.41 60.19,42.63 59.9,42.92 59.9,43.52 59.52,43.9 59.52,44.05 v1(59.52,44.05)
  BOTTOM w0.1: v1(59.52,44.05) 59.52,44.05 59.52,44.09 59.84,44.42 U1.E13
JTAG_RTCK: length 87.1
  TOP w0.1: R56.2 88.14,40.88 87.66,40.41 87.51,40.41 ; v1(110.18,48.14) 110.16,48.12 108.43,48.12 102.29,41.97 98.22,41.97 97.3,42.9 96.05,42.9 95.12,43.83 90.99,43.83 90.12,42.96 90.12,40.65 89.75,40.27 v1(87.51,40.27) 87.51,40.41 ; v1(60.24,44.04) 60.32,43.96 60.32,43.87 60.7,43.49 60.7,42.5 60.59,42.4 60.59,39.38 60.13,38.91 59.22,38 59.22,37.65 59.21,37.64 59.21,35.35 59.22,35.35 59.22,30.94 61.86,28.3 64.04,28.3 64.49,28.3 64.49,28.3 79.19,28.3 84.91,34.01 84.91,37.91 v1(84.65,38.17) ; 87.51,40.41 87.51,40.68 87.19,41 86.65,41 85.69,40.04 84.3,40.04 v1(84.29,40.03)
  BOTTOM w0.1: v1(60.24,44.04) 60.3,44.04 60.64,44.39 U1.E14 ; v1(84.65,38.17) 84.69,38.21 84.69,38.52 84.25,38.96 84.25,39.99 v1(84.29,40.03) ; P2.6 87.99,40.88 87.51,40.41 v1(87.51,40.27) ; v1(110.18,48.14) 110.16,48.16 110.16,48.53 110,48.69 R125.2
JTAG_TCK: length 83.9
  TOP w0.1: v1(56.87,35.1) 56.9,35.1 57.73,35.93 57.73,38.14 57.82,38.23 57.82,38.59 57.82,38.59 57.8,38.62 57.8,41.16 57.99,41.35 57.99,42.66 58.35,43.01 58.35,43.37 58.22,43.5 58.22,44.36 58.66,44.8 v1(58.66,44.81) ; v1(86.93,40.59) 86.05,39.72 85.39,39.72 84.93,39.25 84.08,39.25 83.68,38.85 83.68,33.93 78.9,29.15 62.74,29.15 62.07,29.81 62.07,30.43 61.2,31.3 61.2,32.97 60.42,33.75 59.82,33.75 59.81,33.75 v1(59.84,33.75) ; 94.84,39.15 94.64,39.36 94.64,40.24 ; v1(96.84,42.24) 97.5,41.57 102.46,41.57 107.52,46.64 v1(109.74,46.64) ; 94.64,40.24 94.64,40.24 93.96,39.56 R57.1 ; 94.64,40.24 v1(94.64,40.29)
  BOTTOM w0.1: U1.E11 58.3,44.44 58.66,44.8 v1(58.66,44.81) ; v1(56.87,35.1) 56.87,34.53 57.19,34.21 57.23,34.21 57.26,34.17 59.23,34.17 59.64,33.75 v1(59.84,33.75) ; v1(109.74,46.64) 109.66,46.72 109.66,46.88 109.05,47.48 U15.11 ; v1(96.84,42.24) 96.76,42.24 94.86,40.34 94.7,40.34 v1(94.64,40.29) 94.58,40.34 94.58,40.56 94.26,40.88 P2.5 92.49,41.27 91.11,41.27 90.97,41.41 87.62,41.41 86.93,40.71 v1(86.93,40.59)
JTAG_TDI: length 4.9
  TOP w0.1: R51.2 95.02,41.4 v1(94.74,41.68) 94.74,42.06 R162.2 94.42,42.13 R159.2
  BOTTOM w0.1: P2.3 93.35,41.68 v1(94.74,41.68)
JTAG_TDO: length 4.9
  TOP w0.1: v1(91.04,40.29) 91.05,40.28 91.19,40.28 91.84,39.63 ; 91.84,39.63 R53.2 91.85,40.34 R161.1 ; 91.84,39.63 90.91,39.63
  BOTTOM w0.1: 92.87,39.62 92.21,40.28 91.05,40.28 v1(91.04,40.29)
JTAG_TMS: length 84.7
  TOP w0.1: v1(109.62,45.93) 109.42,45.72 106.89,45.72 102.54,41.37 97.13,41.37 96.23,42.27 v1(96.23,42.28) ; v1(85.51,38.94) 85.45,38.88 85.45,33.98 79.36,27.9 61.69,27.9 58.18,31.41 58.18,32.79 58.62,33.23 58.62,37.89 58.62,37.9 58.62,38.37 59.02,38.77 59.02,39.52 59.44,39.94 59.44,39.94 59.99,40.49 59.99,42.54 59.49,43.04 v1(59.49,43.24) ; v1(84.42,41.5) 85,41.5 86.18,42.68 86.91,42.68 87.4,42.18 v1(87.4,42.1) 87.47,42.17 R55.2
  BOTTOM w0.1: v1(87.4,42.1) 87.45,42.16 P2.4 90.51,42.16 91.19,41.47 94.37,41.47 94.57,41.28 94.91,41.28 95.15,41.51 95.15,42.14 95.38,42.38 96.13,42.38 v1(96.23,42.28) ; v1(59.49,43.24) 59.45,43.24 59.05,43.63 ; U15.12 109.04,46.98 109.24,46.78 109.25,46.78 109.33,46.7 109.33,46.38 109.62,46.1 v1(109.62,45.93) ; v1(85.51,38.94) 85.39,39.06 85.37,39.06 84.72,39.71 84.72,41.16 84.42,41.45 v1(84.42,41.5)
JTAG_TRST_B: length 58.6
  TOP w0.1: v1(84.73,42.03) 84.73,42.12 85.59,42.99 87.05,42.99 v1(87.14,43.08) 87.49,43.43 88.53,43.43 88.54,43.44 R146.1 ; v1(84.5,36.39) 84.5,33.9 79.11,28.5 61.94,28.5 59.42,31.02 59.42,34.38 59.42,34.38 59.42,37.91 60.33,38.82 60.33,38.83 60.8,39.3 60.8,42.32 60.94,42.46 60.94,42.84 60.95,42.88 60.96,42.91 60.96,42.92 60.96,43.05 61.13,43.21 v1(61.13,43.23)
  BOTTOM w0.1: P2.2 87.48,43.43 v1(87.14,43.08) ; U1.D14 60.67,43.63 61.07,43.23 v1(61.13,43.23) ; v1(84.5,36.39) 84.55,36.43 84.55,36.71 85.92,38.07 85.92,39.18 84.92,40.18 84.92,41.84 v1(84.73,42.03)
JTAG_ZB_TDI: length 20.8
  TOP w0.1: v1(109.88,47.33) 107.93,47.33 102.37,41.77 97.95,41.77 97.03,42.7 95.95,42.7 95.25,43.4 94.67,43.4 R162.1 94.46,43.36 R160.1
  BOTTOM w0.1: U15.10 109.12,47.98 109.77,47.33 v1(109.88,47.33)
JTAG_ZB_TDO: length 23.5
  TOP w0.1: R161.2 93.4,40.88 R164.2 94.62,41.23 94.95,40.9 96.36,40.9 96.63,41.17 102.62,41.17 106.97,45.53 109.79,45.53 110.33,46.07 v1(110.33,46.93)
  BOTTOM w0.1: U15.9 109.16,48.48 109.91,47.73 110.06,47.73 110.36,47.44 110.36,47.1 110.33,47.08 v1(110.33,46.93)
LAN_LED_G: length 60
  TOP w0.1: v1(27.14,35.81) 28.66,35.81 34.34,30.12 34.8,30.12 35.82,29.11 35.82,28.73 v1(35.76,28.67) ; v1(30.19,44.12) 30.17,44.1 30.17,43.37 30.02,43.21 30.02,40.91 27.99,38.89 27.99,37.97 27.74,37.71 v1(27.74,37.55) ; v1(37.6,24.99) 37.81,24.99 38.3,24.5 38.3,23.2 42.9,18.6 42.9,14.75 42.45,14.3 42.45,13.95 v1(42.9,13.5)
  BOTTOM w0.1: v1(30.19,44.12) 30.19,44.12 30.19,44.36 30.41,44.57 31.77,44.57 U3.2 ; v1(27.14,35.81) 27.14,35.89 27.47,36.21 27.47,37.1 27.7,37.33 27.7,37.51 v1(27.74,37.55) ; v1(35.76,28.67) 35.76,28.44 35.71,28.39 35.71,26.55 35.87,26.39 35.87,25.79 36.25,25.41 36.5,25.41 36.64,25.27 36.99,25.27 37.27,24.99 v1(37.6,24.99) ; T1.10 47.29,2.96 46.18,1.85 44.7,1.85 41.95,4.6 41.95,12.55 v1(42.9,13.5)
LAN_LED_Y: length 71.1
  TOP w0.1: v1(27.58,38.14) 27.74,38.3 27.74,39.09 29.06,40.41 29.06,41.94 29.77,42.66 29.77,43.92 29.77,44.56 30.1,44.9 v1(30.1,45.12) ; v1(42.9,14.15) 43.1,14.35 43.1,18.75 39.33,22.53 39.33,26.9 38.12,28.1 35.15,28.1 34.2,29.05 34.2,29.95 28.55,35.6 27.67,35.6 27.44,35.38 26.67,35.38 26.45,35.6 v1(26.3,35.6)
  BOTTOM w0.1: v1(26.3,35.6) 26.3,35.79 27.27,36.76 27.27,37.81 27.55,38.1 27.55,38.11 v1(27.58,38.14) ; U3.3 30.05,44.97 30.03,44.98 30.03,45.16 30.1,45.16 v1(30.1,45.12) ; v1(42.9,14.15) 42.75,14.15 41.75,13.15 41.75,4.5 44.65,1.6 53.08,1.6 T1.11
LCD_BL_PWM: length 116.3
  TOP w0.1: v1(57.8,44.08) 57.8,43.71 57.5,43.41 57.5,41.6 56.75,40.85 55.87,40.85 55.02,40 54.69,40 54.16,40 53.72,39.56 53.72,39.28 53.48,39.03 52.31,39.03 50.27,37 45.34,37 45.06,36.72 v1(45.06,36.61) ; v1(39.27,57.48) 38.74,56.96 38.74,46.09 39.18,45.65 39.18,43.88 v1(39.13,43.83) ; FL1.4 91.82,84.4 91.04,83.62 91.04,83.53 90.8,83.29 90.71,83.29 90.08,82.67 v1(90.08,82.4)
  INT1 w0.1: v1(41.65,57.53) 42.52,58.4 42.52,62.57 50.78,70.83 57.9,70.83 60.91,67.82 66.53,67.82 67.61,68.91 68.05,68.91 68.75,69.61 68.75,69.61 68.98,69.84 68.98,69.84 69.2,70.06 69.58,70.06 69.59,70.06 70.31,70.06 72.1,71.85 78.25,71.85 v1(78.7,71.4)
  BOTTOM w0.1: v1(57.8,44.08) 57.74,44.08 57.45,44.38 57.45,44.44 ; v1(39.13,43.83) 39.13,43.65 41.05,41.74 41.99,41.74 42.88,40.84 42.88,38.51 44.79,36.61 v1(45.06,36.61) ; v1(39.27,57.48) 41.47,57.48 41.52,57.53 41.52,57.53 v1(41.65,57.53) ; v1(90.08,82.4) 89.48,82.4 88.01,80.92 88.01,79.54 87.05,78.57 87.05,74.37 85.95,73.28 85.95,73.28 83.42,70.75 80.05,70.75 79.4,71.4 v1(78.7,71.4)
LCD_BL_PWM_EMI: length 38.8
  TOP w0.1: R92.2 105.18,58.13 105.43,58.38 105.43,59.26 104.62,60.07 v1(103.17,60.07) ; v1(99.47,80.89) 99.43,80.94 99.43,81.96 99.91,82.44 99.91,82.58 98.87,83.62 98.48,83.62 98.08,83.23 98.08,83.22 97.5,82.64 95.91,82.64 95.91,82.63 94.71,82.63 94.3,83.03 94.3,83.28 94.22,83.36 94.22,83.97 93.79,84.4 FL1.8
  INT1 w0.1: v1(99.47,80.89) 100.15,80.89 103.73,77.31 103.73,72.03 102.46,70.75 102.46,70.42 102.46,60.66 103.05,60.07 v1(103.17,60.07)
LCD_CARD_PRESENT: length 60.6
  TOP w0.1: v1(97.56,77.38) 98.82,77.38 99.34,76.86 99.34,75.72 99.7,75.35 100.09,75.35 100.37,75.63 J13.83 ; v1(65.1,70.06) 65.04,70.06 65.04,70.08 65.14,70.08 66.77,71.7 68.94,71.7 69.14,71.5 69.67,71.5 70.32,70.85 75.54,70.85 76.48,70.85 77.03,71.4 v1(78.05,71.4)
  INT1 w0.1: v1(85.91,63.05) 89.18,66.32 91.55,66.32 94.87,69.65 94.87,69.92 94.93,69.97 95.16,70.21 95.46,70.5 97.25,72.3 97.25,77.03 97.56,77.34 v1(97.56,77.38)
  BOTTOM w0.1: U17.17 64.88,67.78 64.42,67.78 64.31,67.9 64.31,69.46 64.64,69.79 64.67,69.79 64.91,70.03 64.91,70.06 64.93,70.08 65.04,70.08 65.04,70.06 v1(65.1,70.06) ; v1(85.91,63.05) 84.97,62.12 84.97,61.84 84.74,61.61 84.74,61.6 84.59,61.46 82.97,61.46 82.54,61.88 82.54,68.6 80.79,70.35 79.1,70.35 v1(78.05,71.4)
LCD_CS: length 86.1
  TOP w0.1: FL8.6 105.08,87.91 v1(105.52,87.91)
  INT1 w0.1: v1(105.52,87.91) 105.38,88.05 103.03,88.05 102.57,87.58 101.21,87.58 96.67,83.05 96.67,71.99 95.37,70.7 95.37,70.7 95.14,70.47 95.02,70.35 94.75,70.08 94.67,70 94.67,69.73 92.92,67.99 92.89,67.99 92.35,67.45 86.39,67.45 85.48,66.54 85.28,66.54 82.01,63.27 81.45,63.27 81.03,63.27 80.36,63.27 79.03,61.93 78.52,61.93 78.25,62.21 76.5,62.21 76.5,62.21 75.86,62.21 75.86,62.21 74.28,62.21 74.28,62.21 73.45,62.21 73.45,62.21 71.41,62.21 71.41,62.21 70.91,62.21 70.91,62.21 60.79,62.21 60.79,62.21 59.63,62.21 59.63,62.21 59.37,62.21 58.12,62.2 57.25,63.07 52.91,63.07 51.51,61.67 51.51,61.09 49.18,58.76 49.18,56.98 49.18,56.98 49.18,56.7 50.26,55.62 50.27,55.62 50.91,54.98 50.91,54.29 51.82,53.38 51.82,52.78 52.08,52.51 52.16,52.51 52.21,52.46 52.56,52.46 52.96,52.06 v1(53.03,52.06)
  BOTTOM w0.1: v1(53.03,52.06) 53.03,52.05 53.45,51.63
LCD_CS_CON: length 2.2
  TOP w0.1: R83.1 103.04,81.14 101.63,81.14
LCD_CS_EMI: length 8.2
  TOP w0.1: FL8.10 105.86,86.94 107.06,85.74 107.06,83.05 105.67,81.66 105.61,81.72 104.63,81.72
LCD_D0: length 70.5
  TOP w0.1: FL7.3 92.77,69.69 92.09,69.01 91.54,69.01 91.53,69.02 90.65,69.02 90.43,69.24 v1(90.14,69.24) 89.99,69.09 R119.1
  INT1 w0.1: v1(90.14,69.24) 90.1,69.24 89.78,69.56 86.33,69.56 84.63,67.86 84.63,67.3 81.6,64.27 79.95,64.27 79.4,63.72 78.38,63.72 78.06,63.41 75.36,63.41 75.36,63.41 74.78,63.41 74.78,63.41 72.95,63.41 72.95,63.41 71.9,63.41 71.9,63.41 70.41,63.41 70.41,63.41 61.29,63.41 61.29,63.41 58.87,63.41 56.09,66.19 53.78,66.19 53.5,65.91 52.22,65.91 51.92,65.61 v1(51.92,65.56) ; v1(48.55,51.1) 48.46,51.19 48.46,53.48 48.46,54.97 47.66,55.77 47.66,55.77 47.35,56.07 47.35,59.98 47.39,60.02 47.39,60.73 46.86,61.26 46.86,62.12 47.46,62.72 47.46,63.14 50.55,66.22 50.81,66.22 v1(50.82,66.21)
  BOTTOM w0.1: v1(51.92,65.56) 51.26,66.22 50.84,66.22 v1(50.82,66.21) ; v1(48.55,51.1) 48.52,51.1 48.52,51.1 48.52,51.09 48.52,49.19 49.27,48.44 49.78,48.44 50.09,48.12 50.74,48.12 51.05,48.43 51.05,48.44
LCD_D0_EMI: length 2.4
  TOP w0.1: J13.62 95.9,70.12 94.25,70.12 93.83,69.71 FL7.7
LCD_D1: length 74.4
  TOP w0.1: v1(45.02,61.41) 45.02,61.4 45.74,60.67 45.78,60.67 R120.1 ; v1(49.77,49.4) 50,49.16 51.16,49.16 v1(51.43,48.9) ; 92.77,70.1 92.65,70.1 91.96,69.41 v1(91.71,69.41)
  INT1 w0.1: v1(77.73,64.5) 81.54,64.5 84.43,67.38 84.43,68.03 86.17,69.76 90.39,69.76 90.74,69.41 v1(91.71,69.41) ; v1(45.02,61.41) 45.02,61.75 46.52,63.25 46.52,63.4 51,67.88 51.06,67.88 51.41,68.24 51.41,68.3 51.42,68.3 52.3,69.19 56.98,69.19 60.09,66.07 60.69,66.07 60.69,66.07 61.52,66.07 61.85,66.07 66.63,66.07 66.63,66.07 74.85,66.07 74.85,66.08 75.22,66.08 v1(75.42,66.28)
  BOTTOM w0.1: v1(75.42,66.28) 75.42,66.07 77,64.5 v1(77.73,64.5) ; v1(45.02,61.41) 45.05,61.41 45.73,60.73 45.73,58.49 47.09,57.13 47.09,56.9 48.01,55.98 48.01,52.5 48.8,51.71 48.8,51.71 48.8,51.71 49.16,51.35 49.16,50.84 49.14,50.83 49.14,50.43 49.77,49.8 v1(49.77,49.4) ; v1(51.43,48.9) 51.46,48.87 51.51,48.87 51.84,48.53 U1.K3
LCD_D1_EMI: length 2.4
  TOP w0.1: 93.73,70.1 93.95,70.1 94.48,70.63 J13.64
LCD_D2: length 74
  TOP w0.1: FL7.5 91.7,70.5 R121.1 91.68,70.49 91.65,70.49 v1(91.07,69.91)
  INT1 w0.1: v1(79.18,64.96) 79.68,64.96 79.77,64.87 81.63,64.87 84.17,67.4 84.17,68.05 86.12,70 90.98,70 v1(91.07,69.91) ; v1(75.98,67.09) 75.3,67.09 74.68,66.47 66.46,66.47 66.46,66.47 65.63,66.47 61.35,66.47 60.85,66.47 60.85,66.47 60.26,66.47 57.15,69.59 56.74,69.59 56.74,69.59 52.54,69.59 52.54,69.59 52.21,69.59 52.21,69.59 51.24,69.59 44.52,62.87 44.52,61 44.7,60.82 v1(44.72,60.82)
  BOTTOM w0.1: v1(75.98,67.09) 76.39,67.09 77.53,65.96 78.32,65.96 79.18,65.09 v1(79.18,64.96) ; 51.05,49.24 51.03,49.24 50.71,48.91 49.67,48.91 49.36,49.23 49.36,49.57 49.37,49.58 49.37,49.82 48.93,50.25 48.93,50.91 48.95,50.93 48.95,51.27 48.72,51.5 48.71,51.5 47.81,52.41 47.81,55.9 46.89,56.82 46.89,57.05 45.5,58.44 45.5,60.04 v1(44.72,60.82)
LCD_D2_EMI: length 2.4
  TOP w0.1: FL7.9 93.84,70.5 94.47,71.13 J13.66
LCD_D3: length 67
  TOP w0.1: v1(88.91,71.04) 89.52,71.04 89.91,71.44 R122.1 91.17,70.97 92.7,70.97 FL7.6
  INT1 w0.1: v1(49.55,50.61) 49.55,51.66 48.66,52.54 48.66,53.56 48.66,55.06 47.55,56.17 47.55,59.24 48.06,59.75 48.06,62.69 50.77,65.4 51.16,65.4 51.63,65.87 51.63,65.89 52.13,66.38 56.18,66.38 58.96,63.61 61.37,63.61 61.37,63.6 70.33,63.6 70.33,63.61 71.99,63.61 71.99,63.6 72.87,63.6 72.87,63.61 74.86,63.61 74.86,63.6 75.28,63.6 75.28,63.61 76.23,63.61 77.52,64.9 78.5,64.9 79.04,65.44 81.02,65.44 81.88,66.29 81.88,66.33 86.59,71.04 v1(88.91,71.04)
  BOTTOM w0.1: v1(49.55,50.61) 49.55,50.31 50.28,49.57 51.51,49.57 51.84,49.24
LCD_D3_EMI: length 2.5
  TOP w0.1: FL7.10 93.79,70.91 94.52,71.63 J13.68
LCD_D4: length 69.9
  TOP w0.1: 89.33,72.04 R123.1 ; 89.33,72.04 89.06,72.04 v1(88.93,72.17) ; 89.33,72.04 92.18,72.04 92.18,72.04 92.76,72.04
  INT1 w0.1: v1(77.29,66.78) 77.29,66.56 76.2,65.48 75.76,65.48 75.76,65.47 75.09,65.47 75.08,65.47 66.88,65.47 66.88,65.47 66.13,65.47 65.98,65.47 65.93,65.47 65.64,65.47 65.64,65.47 65.22,65.47 61.76,65.47 60.44,65.47 59.84,65.47 56.73,68.59 54.06,68.59 53.1,67.62 51.02,67.62 46.71,63.31 46.71,63.16 45.86,62.31 45.86,62 45.78,61.93 v1(45.78,61.91) ; v1(88.93,72.17) 87.43,72.17 81.68,66.41 81.68,66.38 81.23,65.94 79.42,65.94 79.41,65.94 79.41,65.94 v1(79.42,65.94)
  BOTTOM w0.1: v1(77.29,66.78) 77.52,66.78 77.53,66.79 78.35,66.79 79.08,66.06 79.33,66.06 79.45,65.94 79.41,65.94 79.41,65.94 v1(79.42,65.94) ; 51.05,50.03 51.05,50.14 50.76,50.43 50.23,50.43 49.94,50.71 49.94,50.85 49.35,51.44 49.35,51.44 48.23,52.57 48.23,56.05 47.29,56.99 47.29,57.22 45.93,58.57 45.93,60.81 45.88,60.87 45.88,61.82 v1(45.78,61.91)
LCD_D4_EMI: length 2.2
  TOP w0.1: 93.72,72.04 94.3,72.04 94.38,72.13 95.91,72.13 J13.70
LCD_D5: length 65.7
  TOP w0.1: v1(81.27,66.55) 80.95,66.55 80.23,65.83 80.23,63.99 v1(78.78,62.53) ; 92.76,72.44 v1(92.01,72.44)
  INT1 w0.1: v1(81.27,66.55) 81.53,66.55 87.73,72.75 91.35,72.75 91.66,72.44 92,72.44 v1(92.01,72.44) ; v1(51.47,50.49) 51.37,50.49 50.6,51.25 50.6,51.28 48.86,53.02 48.86,53.65 48.86,55.15 47.75,56.25 47.75,59.16 48.27,59.68 48.27,61.66 51.28,64.67 52.88,64.67 53.87,63.68 57.18,63.68 57.39,63.47 57.42,63.47 58.28,62.61 58.87,62.61 58.87,62.6 59.2,62.6 59.46,62.6 59.46,62.61 60.96,62.61 60.96,62.6 70.74,62.6 70.74,62.61 71.57,62.61 71.57,62.6 73.29,62.6 73.29,62.61 74.45,62.61 74.45,62.6 75.7,62.6 75.7,62.61 76.66,62.61 76.66,62.6 78.71,62.6 v1(78.78,62.53)
  BOTTOM w0.1: v1(51.47,50.49) 51.47,50.41 U1.M3
LCD_D5_EMI: length 2.3
  TOP w0.1: J13.72 95.89,72.62 94.55,72.62 94.38,72.44 93.72,72.44
LCD_D6: length 87.9
  TOP w0.1: v1(81.5,82.75) 81.8,82.45 81.8,79.25 82.6,78.45 82.6,75.55 81.8,74.75 81.8,73.5 81.55,73.25 81.55,72.8 82.15,72.2 82.15,67.85 v1(81.5,67.2) ; FL6.5 92.18,72.84 92.02,73 v1(91.76,73)
  INT1 w0.1: v1(47.47,61.84) 47.47,62.03 47.87,62.43 47.87,62.9 50.57,65.6 51.07,65.6 51.43,65.96 51.43,65.97 52.04,66.59 55.93,66.59 55.93,66.59 56.3,66.59 59.08,63.81 61.45,63.81 61.45,63.81 70.24,63.81 70.24,63.81 72.07,63.81 72.07,63.81 72.79,63.81 72.79,63.81 74.94,63.81 74.94,63.81 75.2,63.81 75.2,63.81 76.14,63.81 77.44,65.1 78.35,65.1 78.59,65.34 78.59,65.69 78.6,65.71 78.61,65.71 78.61,65.71 78.62,65.72 78.63,65.72 78.86,65.96 78.86,65.96 78.87,65.96 79.92,67.01 80.16,67.01 80.16,67.01 80.49,67.01 81.05,67.01 81.05,67.01 81.27,67.01 81.45,67.2 v1(81.5,67.2) 81.65,67.35 82.04,67.35 87.71,73.02 91.5,73.02 91.51,73 v1(91.76,73)
  BOTTOM w0.1: 51.05,50.84 51.05,50.92 50.73,51.24 49.84,51.24 49.55,51.52 49.55,51.53 48.45,52.63 48.45,56.12 48.07,56.5 48.06,56.5 47.49,57.07 47.49,57.3 46.13,58.66 46.13,60.79 47.18,61.84 v1(47.47,61.84) ; R212.2 84.54,84.05 Q16.1 83.5,83.85 82.65,83 81.75,83 v1(81.5,82.75)
LCD_D6_EMI: length 2.3
  TOP w0.1: J13.74 95.9,73.12 94.5,73.12 94.23,72.84 FL6.9
LCD_D7: length 170.2
  TOP w0.1: FL6.6 92.38,73.25 92,73.63 92,73.67 v1(91.72,73.95) ; R46.1 9.75,101.2 10.35,100.6 18.2,100.6 18.45,100.35 19.3,100.35 19.35,100.3 20.55,100.3 20.75,100.5 27.3,100.5 27.7,100.1 28.3,100.1 28.5,99.9 36.65,99.9 36.85,99.7 37.4,99.7 37.6,99.5 39.45,99.5 39.65,99.7 45.6,99.7 46,99.3 46.55,99.3 46.75,99.1 54.9,99.1 55.1,98.9 55.7,98.9 55.9,98.7 58.4,98.7 58.6,98.9 63.85,98.9 64.25,98.5 64.8,98.5 65,98.3 73.2,98.3 73.4,98.1 73.95,98.1 74.15,97.9 74.2,97.9 74.8,97.3 80.9,97.3 81.45,96.75 81.45,89.75 81.65,89.55 81.65,89 81.75,88.9 81.75,87.8 82,87.55 82,79.45 82.85,78.6 82.85,75.45 82.05,74.65 82.05,73.05 v1(82,73)
  INT1 w0.1: v1(47.59,61.18) 47.55,61.18 47.06,61.67 47.06,62.02 47.27,62.23 47.27,62.24 47.66,62.64 47.66,63.04 50.44,65.82 50.64,65.82 50.66,65.8 50.99,65.8 51.23,66.04 51.23,66.05 51.96,66.78 55.85,66.78 55.85,66.79 56.44,66.79 58.55,64.68 58.78,64.68 58.78,64.68 59.51,64.68 59.51,64.67 60.11,64.67 62.1,64.67 62.43,64.67 65.3,64.67 65.3,64.67 65.51,64.67 65.93,64.67 65.99,64.67 66.13,64.67 67.21,64.67 67.21,64.68 74.74,64.68 74.75,64.67 76.09,64.67 76.1,64.68 76.67,64.68 77.9,65.91 78.53,65.91 78.54,65.93 78.55,65.93 78.66,66.04 78.66,66.04 79.83,67.22 80.24,67.22 80.24,67.21 80.57,67.21 80.9,67.21 84.84,71.15 84.84,72.48 85.2,72.84 85.2,73.4 v1(85.25,73.45) 85.4,73.45 86.1,74.15 91.52,74.15 v1(91.72,73.95)
  BOTTOM w0.1: v1(85.25,73.45) 84.75,72.95 82.05,72.95 v1(82,73) ; U1.P1 49.73,51.63 48.67,52.69 48.67,56.18 48.65,56.2 48.65,56.21 48.53,56.32 48.53,56.32 48.15,56.7 48.14,56.7 47.69,57.16 47.69,57.39 47.46,57.62 47.45,57.62 47.23,57.85 47.23,58.68 46.39,59.51 46.39,60.72 46.78,61.12 47.26,61.12 47.32,61.18 v1(47.59,61.18)
LCD_D7_EMI: length 2.4
  TOP w0.1: FL6.10 93.79,73.25 94.23,73.69 95.85,73.69 J13.76
LCD_D8: length 84.4
  TOP w0.1: RN7.1 82.07,87.88 82.23,87.72 82.23,79.95 82.62,79.55 v1(82.65,79.55) ; FL5.3 92.75,74.35 85.86,74.35 85.67,74.16 85.14,74.16 v1(84.91,74.39)
  INT1 w0.1: v1(84.91,74.39) 84.64,74.12 84.64,71.23 80.82,67.41 80.32,67.41 80.32,67.41 79.75,67.41 78.46,66.12 77.83,66.12 76.58,64.88 76.02,64.88 76.01,64.87 74.83,64.87 74.83,64.88 67.13,64.88 67.13,64.87 66.13,64.87 65.98,64.87 65.98,64.87 65.39,64.87 64.97,64.87 62.34,64.87 62.34,64.87 62.01,64.87 60.19,64.87 59.59,64.87 59.59,64.88 59,64.88 59,64.88 58.86,64.88 56.72,67.01 51.06,67.01 47.27,63.22 47.27,62.8 46.66,62.2 46.66,61.18 46.86,60.98 47.12,60.72 47.19,60.65 47.19,60.1 46.95,59.85 v1(46.95,59.71)
  BOTTOM w0.1: 51.05,51.59 51.05,51.63 50.92,51.63 50.53,52.03 49.62,52.03 48.91,52.74 48.91,56.22 48.87,56.26 48.85,56.28 48.85,56.29 48.62,56.52 48.62,56.52 48.62,56.53 48.23,56.91 48.23,56.91 47.89,57.24 47.89,57.47 47.54,57.82 47.54,59.01 46.95,59.6 v1(46.95,59.71) ; v1(82.65,79.55) 82.9,79.3 82.9,76.62 84.91,74.6 v1(84.91,74.39)
LCD_D8_EMI: length 2.3
  TOP w0.1: J13.78 95.7,74.34 FL5.7
LCD_D9: length 81.5
  TOP w0.1: RN7.2 82.62,82.51 82.43,82.31 82.43,80.86 v1(82.63,80.66) ; v1(84.97,75.67) 85.24,75.4 86.11,75.4 86.76,74.75 FL5.4
  INT1 w0.1: v1(52.43,63.91) 52.18,63.67 52.18,63.19 49.2,60.21 49.19,60.21 48.78,59.8 48.78,59.1 48.78,59.09 48.78,57.15 48.78,57.15 48.78,56.08 49.46,55.4 49.46,54.73 49.46,54.24 51.4,52.3 v1(51.4,52.05) ; v1(84.97,75.67) 84.78,75.67 84.37,75.25 84.37,71.24 80.74,67.61 80.41,67.61 80.41,67.62 80.2,67.62 79.67,67.62 78.38,66.32 77.74,66.32 76.62,65.2 76.62,65.19 76.5,65.07 75.93,65.07 75.93,65.07 74.92,65.07 74.91,65.07 67.04,65.07 67.04,65.07 66.13,65.07 65.98,65.07 65.96,65.07 65.47,65.07 65.47,65.07 65.05,65.07 61.93,65.07 60.27,65.07 59.68,65.07 59.67,65.08 59.08,65.08 56.78,67.38 54.97,67.38 54.96,67.38 54.3,67.38 54.2,67.47 v1(54.03,67.47)
  BOTTOM w0.1: U1.P3 51.82,51.63 v1(51.4,52.05) ; v1(54.03,67.47) 54.08,67.42 54.08,66.61 52.88,65.41 52.88,65.14 52.49,64.75 52.49,63.97 v1(52.43,63.91) ; v1(82.63,80.66) 82.63,80.17 83.1,79.7 83.1,76.78 84.22,75.67 v1(84.97,75.67)
LCD_D9_EMI: length 2.2
  TOP w0.1: J13.80 95.8,74.75 FL5.8
LCD_D10: length 83.8
  TOP w0.1: FL5.5 86.67,75.15 86.22,75.59 85.62,75.59 84.92,76.29 v1(84.34,76.29) ; v1(82.83,81.7) 82.83,81.73 83.12,82.03 RN7.3
  INT1 w0.1: v1(46.79,60.43) 46.41,60.81 46.41,62.23 47.06,62.88 47.06,63.38 50.96,67.28 53.16,67.28 53.8,67.91 54.17,67.91 54.37,67.7 56,67.7 56.2,67.91 57.13,67.91 59.76,65.27 60.36,65.27 61.85,65.27 62.18,65.27 65.56,65.27 65.94,65.27 65.98,65.27 66.13,65.27 66.96,65.27 66.96,65.28 75,65.28 75,65.27 75.84,65.27 75.84,65.28 76.28,65.28 76.28,65.28 76.41,65.28 77.66,66.53 78.29,66.53 79.58,67.81 79.86,67.81 80.66,67.81 84.17,71.32 84.17,76.12 v1(84.34,76.29)
  BOTTOM w0.1: U1.R1 49.5,52.44 49.14,52.8 49.14,56.28 49.12,56.3 49.12,56.31 49.05,56.37 49.05,56.38 48.32,57.1 48.31,57.1 48.31,57.11 48.09,57.33 48.09,57.56 47.78,57.87 47.78,59.49 46.84,60.43 v1(46.79,60.43) ; v1(84.34,76.29) 84.34,76.61 83.3,77.65 83.3,79.8 82.95,80.15 82.95,80.4 83.04,80.48 83.04,81.52 82.93,81.62 82.91,81.62 v1(82.83,81.7)
LCD_D10_EMI: length 2.2
  TOP w0.1: FL5.9 95.9,75.15 J13.82
LCD_D11: length 81.8
  TOP w0.1: v1(84.64,76.91) 85.3,76.91 86.65,75.56 92.17,75.56 92.19,75.54 FL5.6 ; RN7.4 83.62,82.21 83.32,81.9 83.32,80.36 v1(83.39,80.28)
  INT1 w0.1: v1(48.93,60.52) v1(51.78,63.37) ; v1(53.41,68.54) 53.41,68.59 53.6,68.78 56.81,68.78 59.92,65.67 60.52,65.67 61.68,65.67 62.01,65.67 65.72,65.67 65.72,65.67 65.94,65.67 66.13,65.67 66.79,65.67 66.79,65.68 75.17,65.68 75.17,65.67 75.34,65.67 75.34,65.67 75.67,65.67 75.68,65.68 75.97,65.68 76.88,66.59 76.88,66.95 77.12,67.18 77.98,67.18 78.32,67.18 79.15,68.01 79.78,68.01 80.11,68.02 80.36,68.02 80.57,68.01 83.94,71.38 83.94,72.71 83.94,76.46 84.17,76.7 84.29,76.7 84.5,76.91 v1(84.64,76.91)
  BOTTOM w0.1: 51.05,52.44 50.95,52.53 50.95,52.62 50.73,52.84 49.61,52.84 49.34,53.12 49.34,53.45 49.34,53.46 49.34,56.96 48.94,57.37 48.94,60.48 48.95,60.49 48.95,60.5 v1(48.93,60.52) ; v1(51.78,63.37) 51.78,64.21 52.29,64.72 52.29,65 52.62,65.33 52.62,65.44 53.27,66.09 53.27,68.41 v1(53.41,68.54) ; v1(84.64,76.91) 84.64,76.93 84.22,77.35 84.22,77.37 83.5,78.09 83.5,80.17 v1(83.39,80.28)
